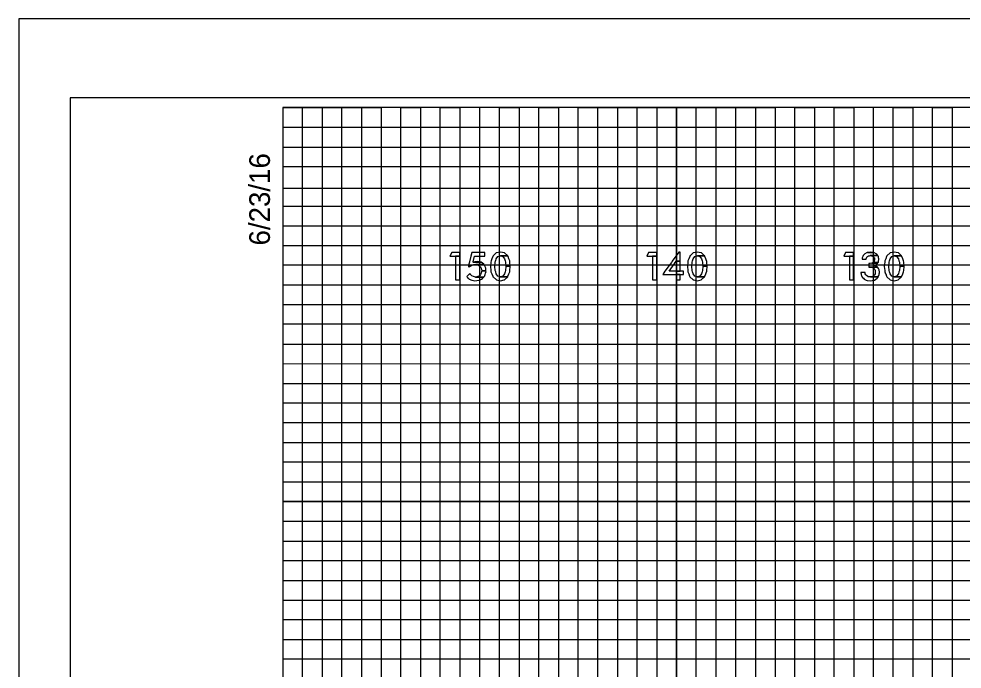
# Model space of a CAD drawing. Extents: x -13 to 323, y -5 to 1431.
# Drawn here: x -13.4 to 34.5, y 401.5 to 434.5 of the extents above; entities that cross this region are included whole.
import ezdxf

# ---------------------------------------------------------------- set-up
doc = ezdxf.new("R2010")
doc.units = 0
for name, color, linetype in [('Prop XS Offset Labels', 7, 'Continuous'), ('Sheet Cross Section CELL', 7, 'Continuous'), ('Sheet Cross Section Grid Major CELL', 7, 'Continuous'), ('Sheet Cross Section Grid Middle CELL', 7, 'Continuous'), ('Sheet Cross Section Grid Minor 1 CELL', 7, 'Continuous'), ('Sheet Cross Section Grid Minor 2 CELL', 7, 'Continuous'), ('Sheet Cutting Line CELL', 7, 'Continuous'), ('Sheet DOT Grid CELL', 7, 'Continuous'), ('Sheet Plot Border Inside CELL', 7, 'Continuous'), ('Sheet Plot Border Outside CELL', 7, 'Continuous')]:
    doc.layers.add(name, color=color, linetype=linetype)

msp = doc.modelspace()

# ---------------------------------------------------------------- linework, layer by layer
at = {"layer": 'Prop XS Offset Labels'}
for points in [[(8.581, 422.641), (8.492, 422.459), (8.99, 422.459), (8.99, 422.641)], [(9.427, 421.94), (9.424, 421.928), (9.495, 421.928), (9.508, 421.94), (9.524, 421.954), (9.595, 421.997), (9.627, 422.007), (9.697, 422.029), (9.811, 422.035), (10.219, 422.035), (10.211, 422.05), (10.076, 422.145), (9.655, 422.145), (9.658, 422.158), (9.658, 422.158), (9.663, 422.178), (9.738, 422.456), (10.263, 422.456), (10.263, 422.641), (9.6, 422.641), (9.554, 422.456), (9.486, 422.178), (9.481, 422.158), (9.478, 422.145), (9.454, 422.05), (9.451, 422.035), (9.449, 422.029), (9.444, 422.007), (9.441, 421.997), (9.431, 421.954)], [(10.851, 421.255), (11.051, 421.214), (11.245, 421.255), (11.256, 421.257), (11.422, 421.409), (11.047, 421.409), (11.038, 421.411), (11.033, 421.413), (10.928, 421.442), (10.841, 421.555), (10.841, 421.556), (10.841, 421.556), (10.813, 421.657), (10.813, 421.659), (10.793, 421.732), (10.792, 421.736), (10.774, 421.939), (10.774, 421.941), (10.774, 421.943), (10.792, 422.145), (10.812, 422.222), (10.813, 422.224), (10.839, 422.322), (10.84, 422.325), (10.928, 422.44), (11.041, 422.469), (11.045, 422.47), (11.055, 422.473), (11.425, 422.473), (11.262, 422.622), (11.254, 422.624), (11.053, 422.668), (11.053, 422.668), (10.845, 422.624), (10.843, 422.622), (10.681, 422.473), (10.678, 422.47), (10.678, 422.469), (10.665, 422.44), (10.618, 422.325), (10.617, 422.322), (10.577, 422.224), (10.576, 422.222), (10.568, 422.145), (10.547, 421.943), (10.547, 421.941), (10.547, 421.939), (10.567, 421.736), (10.568, 421.732), (10.575, 421.659), (10.575, 421.657), (10.616, 421.556), (10.617, 421.555), (10.663, 421.442), (10.675, 421.413), (10.676, 421.411), (10.679, 421.409), (10.848, 421.257)], [(18.581, 422.641), (18.492, 422.459), (18.99, 422.459), (18.99, 422.641)], [(19.411, 421.693), (19.297, 421.534), (20.35, 421.534), (20.35, 421.693), (19.618, 421.693), (19.878, 422.059), (19.935, 422.139), (19.977, 422.199), (20.179, 422.199), (20.179, 422.668), (20.114, 422.668), (19.775, 422.199), (19.733, 422.139), (19.675, 422.059)], [(20.851, 421.255), (21.051, 421.214), (21.245, 421.255), (21.256, 421.257), (21.422, 421.409), (21.047, 421.409), (21.038, 421.411), (21.033, 421.413), (20.928, 421.442), (20.841, 421.555), (20.841, 421.556), (20.841, 421.556), (20.813, 421.657), (20.813, 421.659), (20.793, 421.732), (20.792, 421.736), (20.774, 421.939), (20.774, 421.941), (20.774, 421.943), (20.792, 422.145), (20.812, 422.222), (20.813, 422.224), (20.839, 422.322), (20.84, 422.325), (20.928, 422.44), (21.041, 422.469), (21.045, 422.47), (21.055, 422.473), (21.425, 422.473), (21.262, 422.622), (21.254, 422.624), (21.053, 422.668), (21.053, 422.668), (20.845, 422.624), (20.843, 422.622), (20.681, 422.473), (20.678, 422.47), (20.678, 422.469), (20.665, 422.44), (20.618, 422.325), (20.617, 422.322), (20.577, 422.224), (20.576, 422.222), (20.568, 422.145), (20.547, 421.943), (20.547, 421.941), (20.547, 421.939), (20.567, 421.736), (20.567, 421.732), (20.575, 421.659), (20.575, 421.657), (20.616, 421.556), (20.617, 421.555), (20.663, 421.442), (20.675, 421.413), (20.676, 421.411), (20.679, 421.409), (20.848, 421.257)], [(28.581, 422.641), (28.492, 422.459), (28.99, 422.459), (28.99, 422.641)], [(29.42, 422.315), (29.418, 422.297), (29.626, 422.297), (29.627, 422.315), (29.639, 422.365), (29.64, 422.372), (29.641, 422.373), (29.683, 422.433), (29.688, 422.436), (29.696, 422.44), (29.748, 422.47), (29.785, 422.476), (29.795, 422.478), (29.835, 422.485), (30.217, 422.485), (30.165, 422.561), (30.129, 422.582), (30.128, 422.582), (30.023, 422.644), (29.982, 422.65), (29.69, 422.65), (29.678, 422.644), (29.553, 422.582), (29.536, 422.561), (29.471, 422.485), (29.466, 422.478), (29.465, 422.476), (29.463, 422.47), (29.452, 422.44), (29.45, 422.436), (29.449, 422.433), (29.428, 422.373), (29.427, 422.372), (29.425, 422.365)], [(29.853, 422.668), (29.69, 422.65), (29.982, 422.65)], [(30.007, 422.155), (29.988, 422.131), (30.23, 422.131), (30.246, 422.155), (30.254, 422.201), (30.271, 422.289), (30.272, 422.295), (30.272, 422.297), (30.269, 422.315), (30.26, 422.365), (30.259, 422.372), (30.259, 422.373), (30.259, 422.373), (30.249, 422.433), (30.248, 422.436), (30.248, 422.44), (30.227, 422.47), (30.223, 422.476), (30.222, 422.478), (30.217, 422.485), (29.835, 422.485), (29.901, 422.478), (29.919, 422.476), (29.931, 422.47), (29.986, 422.44), (29.995, 422.436), (29.997, 422.433), (30.04, 422.373), (30.04, 422.372), (30.042, 422.365), (30.051, 422.315), (30.054, 422.297), (30.055, 422.295), (30.056, 422.289), (30.041, 422.201)], [(30.851, 421.255), (31.051, 421.214), (31.245, 421.255), (31.256, 421.257), (31.422, 421.409), (31.047, 421.409), (31.038, 421.411), (31.033, 421.413), (30.928, 421.442), (30.841, 421.555), (30.841, 421.556), (30.841, 421.556), (30.813, 421.657), (30.813, 421.659), (30.793, 421.732), (30.792, 421.736), (30.774, 421.939), (30.774, 421.941), (30.774, 421.943), (30.792, 422.145), (30.812, 422.222), (30.813, 422.224), (30.839, 422.322), (30.84, 422.325), (30.928, 422.44), (31.041, 422.469), (31.045, 422.47), (31.055, 422.473), (31.425, 422.473), (31.262, 422.622), (31.254, 422.624), (31.053, 422.668), (31.053, 422.668), (30.845, 422.624), (30.843, 422.622), (30.681, 422.473), (30.678, 422.47), (30.678, 422.469), (30.665, 422.44), (30.618, 422.325), (30.617, 422.322), (30.577, 422.224), (30.576, 422.222), (30.568, 422.145), (30.547, 421.943), (30.547, 421.941), (30.547, 421.939), (30.567, 421.736), (30.567, 421.732), (30.575, 421.659), (30.575, 421.657), (30.616, 421.556), (30.617, 421.555), (30.663, 421.442), (30.675, 421.413), (30.676, 421.411), (30.679, 421.409), (30.848, 421.257)], [(8.781, 422.459), (8.781, 421.25), (8.99, 421.25), (8.99, 422.459)], [(9.692, 422.158), (9.655, 422.145), (10.076, 422.145), (10.058, 422.158), (9.961, 422.178), (9.75, 422.178)], [(9.888, 422.192), (9.75, 422.178), (9.96, 422.178), (9.888, 422.192)], [(10.083, 421.841), (10.105, 421.721), (10.318, 421.721), (10.307, 421.841), (10.307, 421.841), (10.303, 421.881), (10.284, 421.916), (10.278, 421.928), (10.271, 421.94), (10.263, 421.954), (10.24, 421.997), (10.235, 422.007), (10.223, 422.029), (10.219, 422.035), (9.811, 422.035), (9.838, 422.029), (9.928, 422.007), (9.943, 421.997), (10.003, 421.954), (10.024, 421.94), (10.031, 421.928), (10.038, 421.916), (10.059, 421.881)], [(11.312, 422.145), (11.328, 421.943), (11.555, 421.943), (11.536, 422.145), (11.528, 422.222), (11.527, 422.224), (11.527, 422.224), (11.488, 422.322), (11.488, 422.322), (11.487, 422.325), (11.441, 422.44), (11.44, 422.44), (11.429, 422.469), (11.428, 422.47), (11.425, 422.473), (11.055, 422.473), (11.065, 422.47), (11.068, 422.469), (11.175, 422.44), (11.262, 422.325), (11.265, 422.322), (11.291, 422.224), (11.291, 422.222)], [(18.781, 422.459), (18.781, 421.25), (18.99, 421.25), (18.99, 422.459)], [(19.97, 422.059), (19.97, 421.693), (20.179, 421.693), (20.179, 422.059), (20.179, 422.139), (20.179, 422.199), (19.977, 422.199), (19.973, 422.139)], [(21.312, 422.145), (21.328, 421.943), (21.555, 421.943), (21.536, 422.145), (21.528, 422.222), (21.527, 422.224), (21.527, 422.224), (21.488, 422.322), (21.488, 422.322), (21.487, 422.325), (21.441, 422.44), (21.44, 422.44), (21.429, 422.469), (21.428, 422.47), (21.425, 422.473), (21.055, 422.473), (21.065, 422.47), (21.068, 422.469), (21.175, 422.44), (21.262, 422.325), (21.265, 422.322), (21.291, 422.224), (21.291, 422.222)], [(28.781, 422.459), (28.781, 421.25), (28.99, 421.25), (28.99, 422.459)], [(29.765, 421.956), (29.765, 421.9), (30.194, 421.9), (30.119, 421.956), (30.029, 421.983), (30.095, 422), (30.181, 422.053), (30.2, 422.084), (30.201, 422.085), (30.207, 422.095), (29.915, 422.095), (29.83, 422.085), (29.765, 422.084), (29.765, 422.053), (29.765, 422), (29.765, 421.983)], [(29.988, 422.131), (29.915, 422.095), (30.207, 422.095), (30.23, 422.131)], [(31.312, 422.145), (31.328, 421.943), (31.555, 421.943), (31.536, 422.145), (31.528, 422.222), (31.527, 422.224), (31.527, 422.224), (31.488, 422.322), (31.488, 422.322), (31.487, 422.325), (31.441, 422.44), (31.44, 422.44), (31.429, 422.469), (31.428, 422.47), (31.425, 422.473), (31.055, 422.473), (31.065, 422.47), (31.068, 422.469), (31.175, 422.44), (31.262, 422.325), (31.265, 422.322), (31.291, 422.224), (31.291, 422.222)], [(9.626, 421.233), (9.762, 421.214), (9.959, 421.233), (9.968, 421.237), (10.091, 421.297), (10.091, 421.297), (10.141, 421.321), (10.185, 421.375), (10.204, 421.399), (9.793, 421.399), (9.683, 421.418), (9.682, 421.419), (9.679, 421.42), (9.596, 421.466), (9.586, 421.477), (9.58, 421.483), (9.58, 421.483), (9.529, 421.535), (9.497, 421.585), (9.497, 421.585), (9.451, 421.535), (9.404, 421.483), (9.399, 421.477), (9.39, 421.466), (9.348, 421.42), (9.347, 421.419), (9.348, 421.418), (9.363, 421.399), (9.382, 421.375), (9.445, 421.321), (9.474, 421.297), (9.598, 421.237)], [(9.424, 421.928), (9.482, 421.916), (9.495, 421.928)], [(9.9, 421.418), (9.793, 421.399), (10.204, 421.399), (10.22, 421.418), (10.221, 421.419), (10.222, 421.42), (10.222, 421.42), (10.259, 421.466), (10.268, 421.477), (10.27, 421.483), (10.284, 421.535), (10.299, 421.59), (10.322, 421.674), (10.318, 421.721), (10.105, 421.721), (10.097, 421.674), (10.082, 421.59), (10.047, 421.535), (10.014, 421.483), (10.004, 421.477), (9.987, 421.466), (9.913, 421.42), (9.905, 421.419)], [(11.058, 421.411), (11.047, 421.409), (11.422, 421.409), (11.425, 421.411), (11.426, 421.413), (11.438, 421.442), (11.485, 421.555), (11.485, 421.556), (11.527, 421.657), (11.528, 421.659), (11.535, 421.732), (11.535, 421.736), (11.555, 421.939), (11.556, 421.941), (11.555, 421.943), (11.328, 421.943), (11.328, 421.941), (11.328, 421.939), (11.312, 421.736), (11.312, 421.732), (11.292, 421.659), (11.291, 421.657), (11.264, 421.556), (11.263, 421.555), (11.175, 421.442), (11.063, 421.413)], [(19.97, 421.534), (19.97, 421.25), (20.179, 421.25), (20.179, 421.534)], [(21.058, 421.411), (21.047, 421.409), (21.422, 421.409), (21.425, 421.411), (21.426, 421.413), (21.438, 421.442), (21.485, 421.555), (21.485, 421.556), (21.527, 421.657), (21.528, 421.659), (21.535, 421.732), (21.535, 421.736), (21.555, 421.939), (21.556, 421.941), (21.555, 421.943), (21.328, 421.943), (21.328, 421.941), (21.328, 421.939), (21.312, 421.736), (21.312, 421.732), (21.292, 421.659), (21.291, 421.657), (21.264, 421.556), (21.263, 421.555), (21.175, 421.442), (21.063, 421.413)], [(29.677, 421.229), (29.854, 421.214), (29.936, 421.229), (30.042, 421.248), (30.123, 421.297), (30.187, 421.336), (30.228, 421.399), (30.229, 421.401), (29.849, 421.401), (29.72, 421.416), (29.711, 421.423), (29.639, 421.471), (29.628, 421.479), (29.626, 421.482), (29.608, 421.516), (29.584, 421.562), (29.584, 421.567), (29.58, 421.62), (29.58, 421.625), (29.361, 421.625), (29.362, 421.62), (29.369, 421.567), (29.37, 421.562), (29.377, 421.516), (29.391, 421.482), (29.392, 421.479), (29.395, 421.471), (29.415, 421.423), (29.418, 421.416), (29.425, 421.401), (29.426, 421.399), (29.49, 421.336), (29.53, 421.297), (29.635, 421.248)], [(29.925, 421.416), (29.849, 421.401), (30.229, 421.401), (30.239, 421.416), (30.243, 421.423), (30.243, 421.423), (30.275, 421.471), (30.277, 421.479), (30.277, 421.482), (30.283, 421.516), (30.292, 421.562), (30.293, 421.567), (30.303, 421.62), (30.297, 421.662), (30.285, 421.751), (30.283, 421.763), (30.25, 421.826), (30.223, 421.877), (30.222, 421.88), (30.197, 421.898), (30.194, 421.9), (29.81, 421.9), (29.878, 421.898), (29.951, 421.88), (29.963, 421.877), (30.033, 421.826), (30.07, 421.763), (30.077, 421.751), (30.092, 421.662), (30.088, 421.62), (30.083, 421.567), (30.08, 421.562), (30.057, 421.516), (30.039, 421.482), (30.035, 421.479), (30.025, 421.471), (29.957, 421.423)], [(31.058, 421.411), (31.047, 421.409), (31.422, 421.409), (31.425, 421.411), (31.426, 421.413), (31.438, 421.442), (31.485, 421.555), (31.485, 421.556), (31.527, 421.657), (31.528, 421.659), (31.535, 421.732), (31.535, 421.736), (31.555, 421.939), (31.556, 421.941), (31.555, 421.943), (31.328, 421.943), (31.328, 421.941), (31.328, 421.939), (31.312, 421.736), (31.312, 421.732), (31.292, 421.659), (31.291, 421.657), (31.264, 421.556), (31.263, 421.555), (31.175, 421.442), (31.063, 421.413)]]:
    msp.add_lwpolyline(points, close=True, dxfattribs=at)
at = {"layer": 'Sheet Cross Section CELL'}
msp.add_lwpolyline([(320, 430), (0, 430), (0, 220), (320, 220)], close=True, dxfattribs=at)
at = {"layer": 'Sheet Cross Section Grid Major CELL'}
for p, q in [((10, 430), (0, 430)), ((10, 220), (10, 430)), ((30, 430), (20, 430)), ((20, 430), (20, 220)), ((30, 220), (30, 430))]:
    msp.add_line(p, q, dxfattribs=at)
msp.add_lwpolyline([(0, 420), (320, 420), (320, 410), (0, 410)], dxfattribs=at)
at = {"layer": 'Sheet Cross Section Grid Middle CELL'}
for points in [[(0, 430), (5, 430), (5, 220)], [(15, 220), (15, 430), (25, 430), (25, 220)], [(0, 425), (275, 425)], [(0, 405), (320, 405), (320, 415), (0, 415)]]:
    msp.add_lwpolyline(points, dxfattribs=at)
at = {"layer": 'Sheet Cross Section Grid Minor 1 CELL'}
for p, q in [((0, 429), (260, 429)), ((260, 427.98), (0, 427.98)), ((0, 427.98), (0, 427)), ((0, 427), (260, 427)), ((260, 425.89), (0, 425.89)), ((0, 425.89), (0, 424)), ((0, 424), (320, 424))]:
    msp.add_line(p, q, dxfattribs=at)
for points in [[(0, 423), (270, 423), (320, 423), (320, 422), (0, 422)], [(0, 421), (320, 421), (320, 419), (0, 419)], [(0, 418), (320, 418), (320, 417), (0, 416.98)], [(0, 416), (320, 416), (320, 414), (0, 414)], [(0, 413), (320, 413), (320, 412), (0, 412)], [(0, 411), (320, 411), (320, 409), (0, 409)], [(0, 408), (320, 408), (320, 407), (0, 407)], [(0, 406), (320, 406), (320, 404), (0, 404)], [(0, 403), (320, 403), (320, 402), (0, 402)]]:
    msp.add_lwpolyline(points, dxfattribs=at)
at = {"layer": 'Sheet Cross Section Grid Minor 2 CELL'}
for points in [[(0, 220), (1, 220), (1, 430), (2, 430), (2, 220)], [(2, 220), (3, 220), (3, 430), (4, 430), (4, 220)], [(5, 220), (6, 220), (6, 430), (7, 430), (7, 220)], [(7, 220), (8, 220), (8, 430), (9, 430), (9, 220)], [(10, 220), (11, 220), (11, 430), (12, 430), (12, 220)], [(12, 220), (13, 220), (13, 430), (14, 430), (14, 220)], [(15, 220), (16, 220), (16, 430), (17, 430), (17, 220)], [(17, 220), (18, 220), (18, 430), (19, 430), (19, 220)], [(20, 220), (21, 220), (21, 430), (22, 430), (22, 220)], [(22, 220), (23, 220), (23, 430), (24, 430), (24, 220)], [(25, 220), (26, 220), (26, 430), (27, 430), (27, 220)], [(27, 220), (28, 220), (28, 430), (29, 430), (29, 220)], [(30, 220), (31, 220), (31, 430), (32, 430), (32, 220)], [(32, 220), (33, 220), (33, 430), (34, 430), (34, 220)]]:
    msp.add_lwpolyline(points, dxfattribs=at)
at = {"layer": 'Sheet Cutting Line CELL'}
for p, q in [((323.3, 434.5), (-13.4, 434.5)), ((-13.4, 434.5), (-13.4, 215.5))]:
    msp.add_line(p, q, dxfattribs=at)
at = {"layer": 'Sheet DOT Grid CELL'}
for p, q in [((10, 220), (10, 430)), ((20, 220), (20, 430)), ((30, 220), (30, 430)), ((0, 420), (320, 420)), ((0, 410), (320, 410))]:
    msp.add_line(p, q, dxfattribs=at)
at = {"layer": 'Sheet Plot Border Inside CELL'}
msp.add_lwpolyline([(-10.8, 219.5), (322.4, 219.5), (322.4, 430.5), (-10.8, 430.5)], close=True, dxfattribs=at)
at = {"layer": 'Sheet Plot Border Outside CELL'}
msp.add_lwpolyline([(-13.4, 215.5), (323.3, 215.5), (323.3, 434.5), (-13.4, 434.5)], close=True, dxfattribs=at)

# ---------------------------------------------------------------- texts
at = {"layer": 'Sheet Cross Section CELL'}
msp.add_text('6/23/16', height=1.05, rotation=90, dxfattribs=at).set_placement((-0.65, 423))

doc.saveas('drawing.dxf')
